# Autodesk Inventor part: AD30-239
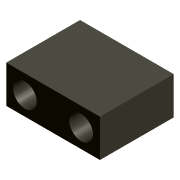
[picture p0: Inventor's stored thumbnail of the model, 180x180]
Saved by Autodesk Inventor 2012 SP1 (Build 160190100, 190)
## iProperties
Shininess: 0.0
Created: 2000-06
Part Number: AD30-239
Project: BONDING PRESS
Description: LATCH BLOCK
Document SubType Name: Modeling
Designer: Ron
Density: 1 g/cm^3
Material: Default
Density: 0.0
Volumn: 0.0
Area: 0.0
PropertySet Name: Model Information
Control State: 0
Master: False
Checked Out: False
Author: Ron
Revision Number: 01
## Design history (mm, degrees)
node "Extrusion1" dims "d2" = 25, "d3" = 0
  sketch "Sketch1"
    geometry: L1 (15.875, -6.35)-(-15.875, -6.35); L2 (-15.875, -6.35)-(-15.875, 6.35); L3 (-15.875, 6.35)-(15.875, 6.35); L4 (15.875, 6.35)-(15.875, -6.35); L5 (-15.875, -6.35)-(15.875, 6.35); 2 further points
    constraints: 10 end point, 2 parallel, 1 coincident, 1 horizontal, 1 midpoint, 1 perpendicular
    dimensions: "d0" = 12.7 distance of L3.end L1.start; "d1" = 31.75 distance between parallel lines of L4 L2
node "Hole1" dims "d5" = 4.2, "d6" = 8, "d7" = 17, "d8" = 60 deg, "d9" = 8, "d10" = 118 deg
  sketch "Sketch2"
    geometry: L1 (15.875, 6.35)-(15.875, -6.35) reference; L2 (-15.875, -6.35)-(-15.875, 6.35) reference; L3 (-15.875, 0)-(-9.525, 0); L4 (-9.525, 0)-(-9.525, 0); L5 (15.875, 0)-(9.525, 0); 2 further points
    constraints: 6 end point, 3 coincident, 2 collinear, 2 midpoint, 1 perpendicular, 1 point on line
    dimensions: "d4" = 19.05 distance of point (9.525, 0) point (-9.525, 0)
body "Solid1"
